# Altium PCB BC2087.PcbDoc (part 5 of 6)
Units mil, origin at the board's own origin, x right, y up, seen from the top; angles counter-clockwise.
Board outline 7401.57 x 1181.1 mil, 6 copper layers (Top Copper, Signal Layer 1, Signal Layer 2, Signal Layer 3, Signal Layer 4, Bottom Copper), stack 62.874 mil thick; 302 components, 237 nets, 1184 pads, 867 vias.
Unrouted connection lines stored in the file: 315.
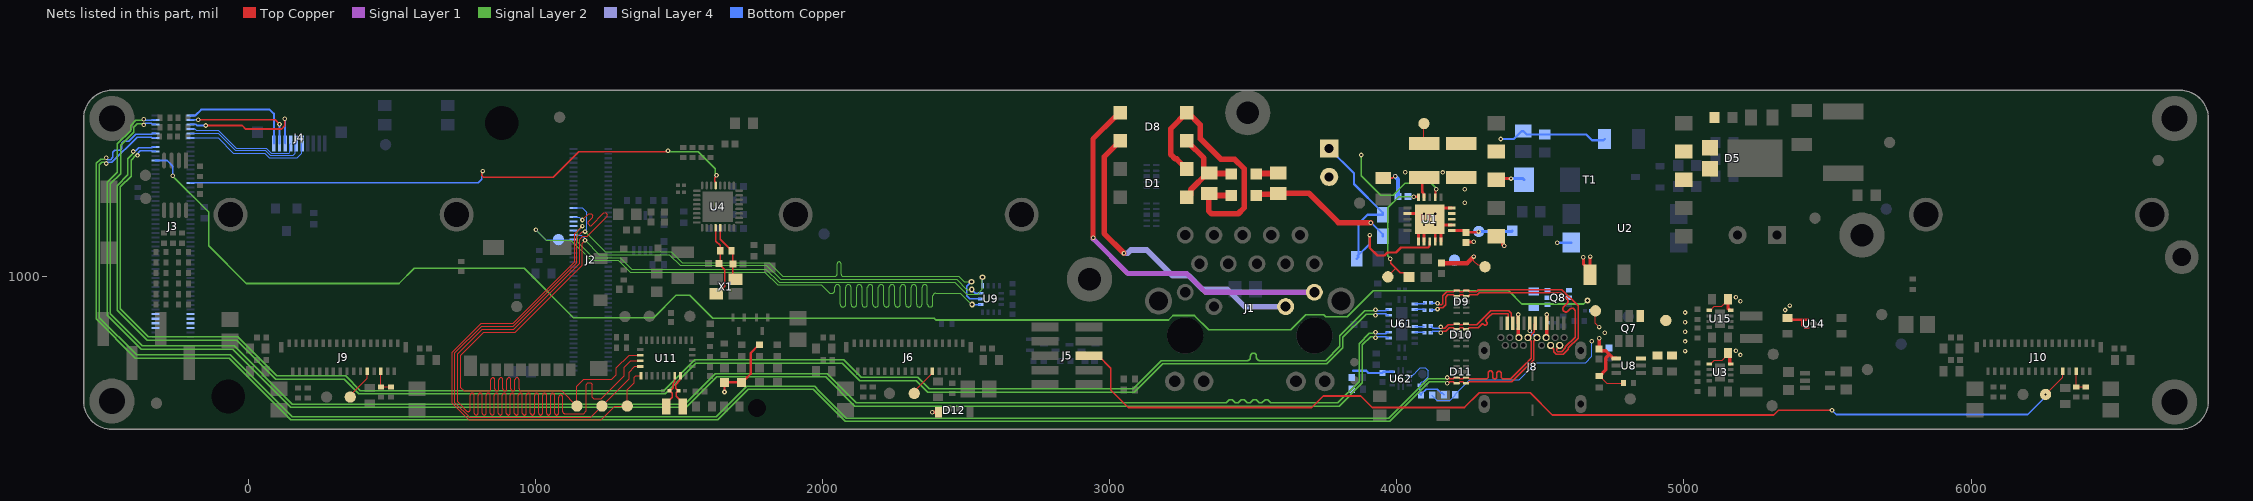
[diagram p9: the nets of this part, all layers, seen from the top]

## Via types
v1: diameter 20, hole 10, Top Copper to Bottom Copper, 273 vias
v2: diameter 16, hole 8, Top Copper to Bottom Copper, tented both sides, 243 vias
v3: diameter 15.98, hole 7.99, Top Copper to Bottom Copper, tented both sides, 201 vias
v4: diameter 18, hole 8, Top Copper to Bottom Copper, tented both sides, 70 vias
v5: diameter 16, hole 7.95, Top Copper to Bottom Copper, tented both sides, 36 vias
v6: diameter 20, hole 10, Top Copper to Bottom Copper, tented both sides, 26 vias
v7: diameter 16, hole 8, Top Copper to Bottom Copper, 17 vias
v8: diameter 19.68, hole 11.81, Top Copper to Bottom Copper, tented both sides, 1 vias

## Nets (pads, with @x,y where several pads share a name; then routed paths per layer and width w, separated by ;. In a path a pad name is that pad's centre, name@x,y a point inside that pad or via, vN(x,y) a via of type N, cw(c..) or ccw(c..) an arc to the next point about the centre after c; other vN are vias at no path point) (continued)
SDS_TXD_P: J3.69 U4.13 | length 2009.5
  Top Copper w5.12: v2(816,1368.72) 812.42,1365.14 812.42,1353.47 818.14,1347.75 1061.94,1347.75 1149.45,1435.26 1457.26,1435.26 v3(1461,1439) ; U4.13@1627.27,1318.86 1627.27,1329.45 1624.5,1332.21 1624.5,1345.97 1629.92,1351.39 v3(1629.92,1354.33)
  Signal Layer 2 w5.12: v3(1461,1439) 1463.32,1436.68 1566.64,1436.68 1625.93,1377.39 1625.93,1358.32 v3(1629.92,1354.33)
  Bottom Copper w5.12: J3.69@-202.76,1326.77 -201.77,1327.76 -189.57,1327.76 -189.07,1328.25 288.17,1328.25 799.25,1328.25 812,1341 812,1364.72 v2(816,1368.72)
SLASEL1: J10.6 R35.2 R36.2 | length 88.2
  Top Copper w4: J10.6@6366.29,671.88 R36.2@6366.29,617.13 R35.2@6399.75,617.13
SLASEL2: J9.6 R40.2 R42.2 | length 89.5
  Top Copper w4: J9.6@460.77,671.88 460.77,617.55 R42.2@461.19,617.13 R40.2@495.79,617.13
SP1: D8.2 J1.13 | length 1092.3
  Top Copper w19.68: D8.2@3035.79,1473.77 2980.31,1418.29 2980.31,1151.57 v3(3049.21,1082.68)
  Signal Layer 4 w19.68: v3(3049.21,1082.68) 3062.01,1082.68 3073.07,1093.74 3128.58,1093.74 3218.38,1003.94 3275.59,1003.94 3322.83,956.69 3409.45,956.69 3469.62,896.52 J1.13@3612.6,896.52
SP2: D8.3 J1.14 | length 1328.6
  Top Copper w17.72: v3(2941.93,1136.81) 2940.94,1137.8 2940.94,1480.32 3018.06,1557.43 3021.03,1557.43 D8.3@3035.79,1572.19
  Signal Layer 1 w17.72: v3(2941.93,1136.81) 2941.93,1132.87 3063.52,1011.28 3268.25,1011.28 3333.01,946.52 J1.14@3712.6,946.52
SPI_BMI270_CS_1V8: J2.60 TP30.1 U9.12 | length 3044.7
  Signal Layer 2 w4: v2(1001,1164) 1036.49,1128.51 1122.79,1128.51 1193.3,1058 1288.3,1058 1329.3,1017 1797.81,1017 1842.81,972 1995.57,972 2024.45,943.12 2030.43,943.12 2032.43,943.12 ccw(c2032.43,952.62) 2041.93,952.62 2041.93,963.15 cw(c2051.43,963.15) 2060.93,963.15 2060.93,904.44 ccw(c2070.43,904.44) 2079.93,904.44 2079.93,963.15 cw(c2089.43,963.15) 2098.93,963.15 2098.93,904.44 ccw(c2108.43,904.44) 2117.93,904.44 2117.93,963.15 cw(c2127.43,963.15) 2136.93,963.15 2136.93,904.44 ccw(c2146.43,904.44) 2155.93,904.44 2155.93,963.15 cw(c2165.43,963.15) 2174.93,963.15 2174.93,904.44 ccw(c2184.43,904.44) 2193.93,904.44 2193.93,963.15 cw(c2203.43,963.15) 2212.93,963.15 2212.93,904.44 ccw(c2222.43,904.44) 2231.93,904.44 2231.93,963.15 cw(c2241.43,963.15) 2250.93,963.15 2250.93,904.44 ccw(c2260.43,904.44) 2269.93,904.44 2269.93,963.15 cw(c2279.43,963.15) 2288.93,963.15 2288.93,904.44 ccw(c2298.43,904.44) 2307.93,904.44 2307.93,963.15 cw(c2317.43,963.15) 2326.93,963.15 2326.93,904.44 ccw(c2336.43,904.44) 2345.93,904.44 2345.93,963.15 cw(c2355.43,963.15) 2364.93,963.15 2364.93,904.75 ccw(c2374.43,904.75) 2383.93,904.75 2383.93,933.62 cw(c2393.43,933.62) 2393.43,943.12 2411.45,943.12 2479.88,943.12 2519.46,903.54 v6(2520.46,903.54)
  Bottom Copper w4: v2(1001,1164) 1035.08,1129.92 TP30.1@1079.49,1129.92 J2.60@1131.69,1129.92
  Bottom Copper w5: v6(2520.46,903.54) U9.12@2549.86,903.54
SPI_BNO08x_CS_1V8: J2.70 U11.18 | length 3669.8
  Top Copper w4: v2(1162.95,1198.42) 1184.46,1219.93 1192.81,1219.93 1198.57,1214.17 1198.57,1207.57 1183,1192 1183,1185.1 1189.1,1179 1194.29,1179 1238.09,1222.8 1245.03,1222.8 1249,1218.83 1249,1212.19 1179.32,1142.51 1164.81,1142.51 1152.76,1130.46 1152.76,1046.76 924.16,818.16 814.16,818.16 728.34,732.34 728.34,564.43 728.42,564.36 760.05,532.72 ccw(c765,537.67) 772,537.67 772,588 cw(c779,588) 786,588 786,525.93 ccw(c793,525.93) 800,525.93 800,588 cw(c807,588) 814,588 814,525.93 ccw(c821,525.93) 828,525.93 828,588 cw(c835,588) 842,588 842,525.93 ccw(c849,525.93) 856,525.93 856,588 cw(c863,588) 870,588 870,525.93 ccw(c877,525.93) 884,525.93 884,588 cw(c891,588) 898,588 898,525.93 ccw(c905,525.93) 912,525.93 912,588 cw(c919,588) 926,588 926,525.93 ccw(c933,525.93) 940,525.93 940,588 cw(c947,588) 954,588 954,525.93 ccw(c961,525.93) 968,525.93 968,588 cw(c975,588) 982,588 982,525.93 ccw(c989,525.93) 996,525.93 996,588 cw(c1003,588) 1010,588 1010,525.93 ccw(c1017,525.93) 1024,525.93 1024,588 cw(c1031,588) 1038,588 1038,525.93 ccw(c1045,525.93) 1052,525.93 1052,588 cw(c1059,588) 1066,588 1066,525.93 ccw(c1073,525.93) 1080,525.93 1080,581.69 cw(c1087,581.69) 1094,581.69 1094,531 ccw(c1101,531) 1101,524 1117,524 1167,524 1176,533 1176,625 1182,631 1192.65,631 1197.86,625.79 1197.86,580.14 1202,576 1217.12,576 1228,576 1307.86,655.86 1307.86,684.83 1330.71,707.68 U11.18@1363.96,707.68
  Bottom Copper w4: J2.70@1131.69,1208.66 1152.71,1208.66 v2(1162.95,1198.42)
SPI_MISO_1V8: J2.64 TP28.1 U9.1 U11.20 | length 3323.9
  Top Copper w4: v5(1162.95,1177.17) 1136,1150.21 1136,1052.63 921.37,838 810.35,838 710,737.65 710,560.15 767.22,502.93 1228.93,502.93 1276,550 TP28.1@1319,550 1319,607 1343,631 1343,651 1348,656 U11.20@1366.42,656
  Signal Layer 2 w4: v5(1162.95,1177.17) 1145.66,1159.87 1145.66,1121.99 1200.65,1067 1294.22,1067 1334.22,1027 1801.42,1027 1847.77,980.65 2460.58,980.65 2501.26,939.97 2539.97,939.97 2556.26,956.26 v6(2556.26,998.74)
  Bottom Copper w4: J2.64@1131.69,1161.42 1148.14,1161.42 1162.95,1176.23 v5(1162.95,1177.17)
  Bottom Copper w5: U9.1@2556.26,969 v6(2556.26,998.74)
SPI_MOSI_1V8: J2.62 TP29.1 U9.14 U11.17 | length 3358.1
  Top Copper w4: v5(1172,1127.43) 1162,1117.43 1162,1040.5 929.5,808 819.35,808 739,727.65 739,614.42 750.42,603 809,603 837,603 ccw(c837,610) 844,610 844,641.53 cw(c851,641.53) 858,641.53 858,610 ccw(c865,610) 872,610 872,641.53 cw(c879,641.53) 886,641.53 886,610 ccw(c893,610) 900,610 900,641.53 cw(c907,641.53) 914,641.53 914,610 ccw(c921,610) 928,610 928,641.53 cw(c935,641.53) 942,641.53 942,610 ccw(c949,610) 949,603 965,603 1091,603 TP29.1@1144,550 1144,620 1166.72,642.72 1264.64,642.72 1280.82,658.9 1280.82,682.82 1325.36,727.36 U11.17@1363.96,727.36
  Signal Layer 2 w4: v5(1172,1127.43) 1221.43,1078 1466.08,1078 1504.08,1040 1804,1040 1853,991 2467,991 2502,956 v6(2519,956)
  Bottom Copper w4: J2.62@1131.69,1145.67 1158.45,1145.67 1172,1132.12 v5(1172,1127.43)
  Bottom Copper w5: v6(2519,956) 2532.09,942.91 U9.14@2549.86,942.91
SPI_SCK_1V8: J2.74 TP27.1 U9.13 U11.19 | length 3343.5
  Top Copper w4: v5(1172,1157.91) 1162.39,1157.91 1144,1139.53 1144,1049.31 922.69,828 811.66,828 719,735.34 719,562.46 770.53,510.93 1191.93,510.93 TP27.1@1231,550 1326,645 1326,668 1345.99,687.99 U11.19@1363.96,687.99
  Signal Layer 2 w4: v5(1172,1157.91) 1241.91,1088 1471.65,1088 1510.86,1048.79 1814.21,1048.79 1860.7,1002.3 2041,1002.3 2043,1002.3 ccw(c2043,1009.3) 2050,1009.3 2050,1045.3 cw(c2057,1045.3) 2064,1045.3 2064,1009.3 ccw(c2071,1009.3) 2071,1002.3 2085,1002.3 2473.11,1002.3 2492.41,983 v6(2518,983)
  Bottom Copper w4: J2.74@1131.69,1240.16 1162.47,1240.16 1178,1224.63 1178,1166.25 1172,1160.25 v5(1172,1157.91)
  Bottom Copper w5: v6(2518,983) 2517.48,983 2502,967.52 2502,934 2512.77,923.23 U9.13@2549.86,923.23
SPI_SIO2: J2.66
SPI_SIO3: J2.68
STRB2: J9.10 TP31.1 | length 114.9
  Top Copper w4: TP31.1@354.18,581.57 354.18,588.23 413.53,647.58 J9.10@413.53,671.88
STRBL: J5.6 J10.10 TP15.1 | length 3690.1
  Top Copper w4: v2(6259.84,590.55) 6319.04,649.75 J10.10@6319.04,671.88
  Top Copper w6: J5.6@2928.15,725.39 2960.43,725.39 3003.5,682.33 3003.5,606.24 3064.74,545 3703.23,545 3743.23,585 3874,585 3914,545 4235.28,545 4286.74,596.46 4464.32,596.46 4541.9,518.88 5312.52,518.88 5329.27,535.62 v2(5515.75,535.62)
  Bottom Copper w6: v2(5515.75,535.62) 5530.62,520.75 6198.06,520.75 6257.93,580.62 6257.93,588.64 v2(6259.84,590.55)
STROBE3: J6.10 TP33.1 | length 103.5
  Top Copper w4: TP33.1@2318.9,594.49 2318.9,601.85 2382.03,664.99 J6.10@2382.03,671.88
SWO: D4.2 T1.3 U1.18 | length 95.2
  Top Copper w10: T1.3@4351.66,1337.72 4356.46,1342.52 v3(4397.64,1342.52)
  Bottom Copper w10: v3(4397.64,1342.52) 4439.26,1342.52 D4.2@4443.19,1338.58
SYS_RST: J3.89 J4.6 | length 457.2
  Bottom Copper w4.02: J3.89@-202.76,1484.25 -106.42,1484.25 -53.5,1431.33 56.79,1431.33 72.82,1415.3 169.06,1415.3 185.08,1431.32 185.08,1463.7 J4.6@186.38,1465
TCK: J3.97 J4.2 | length 383.7
  Top Copper w6: v3(-175.74,1547.24) 92.32,1547.24 v3(107.64,1531.93)
  Bottom Copper w6: J3.97@-202.76,1547.24 v3(-175.74,1547.24) ; J4.2@107.64,1465 v3(107.64,1531.93)
TDI: J3.95 J4.3 | length 452
  Top Copper w6: v3(-149.61,1527.56) -21.88,1527.56 -9.25,1514.93 114.68,1514.93 125.98,1526.24 v3(125.98,1551.18)
  Bottom Copper w6: J3.95@-202.76,1531.5 -184.03,1531.5 -180.09,1527.56 -152.84,1527.56 v3(-149.61,1527.56) ; v3(125.98,1551.18) 126.65,1550.51 126.65,1465.67 J4.3@127.32,1465
TDO: J3.91 J4.5 | length 436.1
  Bottom Copper w4.02: J3.91@-202.76,1500 -105.82,1500 -46.63,1440.8 58.66,1440.8 76.14,1423.32 155.01,1423.32 163.01,1431.32 163.01,1461.32 J4.5@166.69,1465
TMS: J3.99 J4.1 | length 408.1
  Bottom Copper w7.09: J3.99@-202.76,1562.99 -184.8,1562.99 -165.11,1582.68 -68.7,1582.68 73.62,1582.68 87.95,1568.34 J4.1@87.95,1465
TRST: J3.93 J4.4 | length 415.4
  Bottom Copper w4.02: J3.93@-202.76,1515.75 -186.7,1515.75 -181.51,1510.56 -105.05,1510.56 -43.31,1448.82 61.98,1448.82 79.46,1431.33 141.82,1431.33 144.17,1433.69 144.17,1462.16 J4.4@147.01,1465
TXB1_N: C209.2 U61.16 | length 34.4
  Bottom Copper w5.12: U61.16@4062.64,827.06 4071.68,827.06 4071.89,826.85 4094.13,826.85 C209.2@4096.1,828.82
TXB1_P: C208.2 U61.17 | length 34.4
  Bottom Copper w5.12: U61.17@4062.64,807.38 4062.85,807.17 4094.13,807.17 C208.2@4096.1,805.2
TXB_N: C209.1 D10.1 D10.10 J8.A3 | length 363
  Top Copper w5.12: v3(4153.14,825.78) 4157.66,821.26 4166.9,821.26 4178.2,832.57 4196.41,832.57 4199.41,835.56 4199.41,835.91 4200.79,837.29 D10.1@4207.97,837.29 4215.16,837.29 4216.54,835.91 4216.54,835.56 4219.53,832.57 4229.29,832.57 4232.28,835.56 4232.28,835.91 4233.66,837.29 D10.10@4240.85,837.29 4248.03,837.29 4249.41,835.91 4249.41,835.56 4252.41,832.57 4277.74,832.57 4327.79,882.62 4389.82,882.62 4398.82,873.62 4398.82,860.53 4403.54,855.8 J8.A3@4403.54,838.08
  Bottom Copper w5.12: C209.1@4118.15,828.82 4118.94,828.82 4126.76,821 4148.36,821 v3(4153.14,825.78)
TXB_P: C208.1 D10.2 D10.9 J8.A2 | length 360.2
  Top Copper w5.12: v3(4153.14,805.79) 4158.37,811.02 4171.14,811.02 4182.44,822.33 4196.41,822.33 4199.41,819.33 4199.41,818.98 4200.79,817.6 D10.2@4207.97,817.6 4215.16,817.6 4216.54,818.98 4216.54,819.33 4219.53,822.33 4229.29,822.33 4232.28,819.33 4232.28,818.98 4233.66,817.6 D10.9@4240.85,817.6 4248.03,817.6 4249.41,818.98 4249.41,819.33 4252.41,822.33 4281.97,822.33 4282.83,823.19 4293.83,834.19 cw(c4298.42,829.59) 4303.02,834.19 4303.28,833.92 ccw(c4307.88,838.51) 4312.47,833.92 ccw(c4307.88,838.51) 4312.47,843.11 4312.2,843.37 cw(c4316.8,847.97) 4312.2,852.56 4322.3,862.66 4332.03,872.38 4385.58,872.38 4388.58,869.38 4388.58,860.53 4383.86,855.8 J8.A2@4383.86,838.08
  Bottom Copper w5.12: C208.1@4119,805.26 4124.5,810.76 4148.17,810.76 v3(4153.14,805.79)
TXC1_N: C212.2 U61.12 | length 36.2
  Bottom Copper w5.12: U61.12@4062.64,905.8 4063.47,906.63 4094.47,906.63 C212.2@4097.28,909.45
TXC1_P: C211.2 U61.13 | length 35.8
  Bottom Copper w5.12: U61.13@4062.64,886.12 4071.06,886.12 4071.89,886.95 4094.07,886.95 C211.2@4096.89,884.13
TXC_N: C212.1 D9.1 D9.10 J8.B3 | length 838
  Top Copper w5.12: v3(4141.47,908) 4146.23,903.24 4155.43,903.24 4159.28,907.08 4159.28,933.95 4173.36,948.03 4197.46,948.03 4200.46,951.03 4200.46,951.38 4201.84,952.76 D9.1@4209.02,952.76 4216.21,952.76 4217.59,951.38 4217.59,951.03 4220.58,948.03 4230.33,948.03 4233.33,951.03 4233.33,951.38 4234.71,952.76 D9.10@4241.9,952.76 4249.08,952.76 4250.46,951.38 4250.46,951.03 4253.46,948.03 4276.07,948.03 4283.28,955.24 4574.99,955.24 4631.1,899.12 4631.1,786.06 4597.64,752.59 4597.64,748.59 4578.8,729.76 4555.06,729.76 4546.06,738.75 4546.06,748.08 4535.43,758.71 J8.B3@4535.43,761.31
  Bottom Copper w5.12: C212.1@4119.33,909.45 4120.31,908.46 4141,908.46 v3(4141.47,908)
TXC_P: C211.1 D9.2 D9.9 J8.B2 | length 833.2
  Top Copper w5.12: v3(4141.47,888.02) 4146.45,893 4159.67,893 4169.51,902.84 4169.51,929.71 4177.6,937.8 4197.46,937.8 4200.46,934.8 4200.46,934.45 4201.84,933.07 D9.2@4209.02,933.07 4216.21,933.07 4217.59,934.45 4217.59,934.8 4220.58,937.8 4230.33,937.8 4233.33,934.8 4233.33,934.45 4234.71,933.07 D9.9@4241.9,933.07 4249.08,933.07 4250.46,934.45 4250.46,934.8 4253.46,937.8 4280.31,937.8 4287.52,945 4570.75,945 4576.76,938.99 4578.57,937.18 4593.32,922.43 cw(c4585.94,915.05) 4593.32,907.67 4581.12,895.48 ccw(c4588.5,888.1) 4581.12,880.72 ccw(c4588.5,888.1) 4595.88,880.72 4603.06,887.9 cw(c4610.43,880.52) 4620.87,880.52 4620.87,850.61 4620.87,790.3 4587.4,756.83 4587.4,752.83 4574.56,739.99 4559.3,739.99 4556.3,742.99 4556.3,748.08 4566.93,758.71 J8.B2@4566.93,761.31
  Bottom Copper w5.12: C211.1@4118.94,884.13 4120.86,886.06 v3@4139.02,886.06
USB_D_N: D11.2 D11.9 J3.90 J8.A7 J8.B7 | length 6316.1
  Top Copper w5.12: v2(4176,649.76) 4178.94,649.76 4183.83,644.88 4196.41,644.88 4199.41,647.88 4199.41,648.23 4200.79,649.61 D11.9@4207.97,649.61 4215.16,649.61 4216.54,648.23 4216.54,647.88 4219.53,644.88 4229.29,644.88 4232.28,647.88 4232.28,648.23 4233.66,649.61 D11.2@4240.85,649.61 4248.03,649.61 4249.41,648.23 4249.41,647.88 4252.41,644.88 4262.48,644.88 4262.54,644.94 4308.33,644.94 4310.89,644.94 ccw(c4310.89,652.42) 4318.37,652.42 4318.37,665.52 cw(c4325.85,665.52) 4333.33,665.52 4333.33,652.42 ccw(c4340.81,652.42) 4348.29,652.42 4348.29,663.75 cw(c4355.77,663.75) 4363.25,663.75 4363.25,652.42 ccw(c4370.73,652.42) 4370.73,644.94 4396.18,644.94 4417.41,666.17 4467.32,716.08 4467.32,775.64 4456.69,786.27 J8.B7@4456.69,788.87 4459.62,788.87 4478.94,808.19 4478.94,834.74 J8.A7@4482.28,838.08
  Signal Layer 2 w5.17: v5(-496,1395) -500.47,1399.47 -511.03,1399.47 -519.68,1390.82 -519.68,858.27 -389.76,728.35 -63.35,728.35 151.94,513.06 1629.42,513.06 1735.42,619.06 1971.49,619.06 1988.19,602.36 2082.68,507.87 3971.23,507.87 4108.65,645.29 4168.6,645.29 4173.07,649.76 v2(4176,649.76)
  Bottom Copper w5.12: v5(-496,1395) -492.24,1398.76 -476.7,1398.76 -388.46,1487.01 -337.01,1487.01 -334.25,1484.25 J3.90@-324.02,1484.25 ; J8.B7@4456.69,786.27 J8.B7@4456.69,788.87
USB_D_P: D11.1 D11.10 J3.92 J8.A6 J8.B6 | length 6321.6
  Top Copper w5.12: v2(4176,629.76) 4178.94,629.76 4183.83,634.65 4196.41,634.65 4199.41,631.65 4199.41,631.3 4200.79,629.92 D11.10@4207.97,629.92 4215.16,629.92 4216.54,631.3 4216.54,631.65 4219.53,634.65 4229.29,634.65 4232.28,631.65 4232.28,631.3 4233.66,629.92 D11.1@4240.85,629.92 4248.03,629.92 4249.41,631.3 4249.41,631.65 4252.41,634.65 4266.72,634.65 4266.78,634.71 4400.42,634.71 4477.56,711.84 4477.56,775.64 4488.19,786.27 J8.B6@4488.19,788.87 ; J8.A6@4462.6,855.8 J8.A6@4462.6,838.08 4463.03,837.65 v3(4463.03,812.88)
  Signal Layer 2 w5.17: v5(-496,1415) -500.47,1410.53 -515.61,1410.53 -530.75,1395.4 -530.75,853.69 -394.35,717.28 -67.93,717.28 147.36,502 1634,502 1664.14,532.14 1740,608 1966.91,608 2078.1,496.81 3975.81,496.81 4113.23,634.23 4168.6,634.23 4173.07,629.76 v2(4176,629.76)
  Bottom Copper w5.12: v5(-496,1415) -490,1409 -480.94,1409 -474.96,1414.98 -473.15,1416.79 -473.15,1433.76 -466.08,1440.83 -449.11,1440.83 -441.33,1448.61 -441.33,1465.58 -434.26,1472.65 -417.29,1472.65 -405.47,1484.47 -392.7,1497.24 -337.01,1497.24 -334.25,1500 J3.92@-324.02,1500 ; v3(4463.03,812.88) 4463.61,812.88 4487.61,788.87 J8.B6@4488.19,788.87
USB_RX_N: J3.96 U61.4 | length 5660.3
  Signal Layer 2 w5.17: v2(-365,1529.37) -369.47,1533.84 -388.16,1533.84 -400.16,1521.84 -400.16,1503.6 -445.94,1457.83 -445.94,1360 -481,1324.94 -481,871 -369.58,759.58 -50.41,759.58 152.11,557.06 1520.06,557.06 1626.06,663.06 2014.94,663.06 2035,643 2117,561 3400,561 3405.99,561 3416.67,571.68 3426.67,571.68 3437.35,561 3447.35,561 3458.02,571.68 3468.02,571.68 3478.7,561 3488.7,561 3499.38,571.68 3509.38,571.68 3520.06,561 3530.06,561 3540.74,571.68 3550.74,571.68 3561.41,561 3564,561 3794.36,561 3868.94,635.58 3868.94,767.86 3904.14,803.06 3921.03,803.06 v5(3925.65,807.69)
  Bottom Copper w5.12: v2(-365,1529.37) -358.37,1536 -338.76,1536 -334.25,1531.5 J3.96@-324.02,1531.5 ; v5(3925.65,807.69) 3930.69,802.65 3960.47,802.65 3965.2,807.38 U61.4@3972.09,807.38
USB_RX_P: J3.98 U61.3 | length 5658.4
  Signal Layer 2 w5.17: v2(-365,1549.37) -369.47,1544.9 -392.74,1544.9 -411.22,1526.42 -411.22,1508.87 -457,1463.09 -457,1364.58 -492.06,1329.52 -492.06,866.42 -374.16,748.52 -54.99,748.52 147.53,546 1524.64,546 1630.64,652 2010.36,652 2112.42,549.94 3798.94,549.94 3880,631 3880,763.28 3908.72,792 3921.34,792 v5(3925.65,787.69)
  Bottom Copper w5.12: v2(-365,1549.37) -361.87,1546.24 -335.26,1546.24 -334.25,1547.24 J3.98@-324.02,1547.24 ; v5(3925.65,787.69) 3930.38,792.42 3960.47,792.42 3965.2,787.69 U61.3@3972.09,787.69
USB_TX_N: J3.84 U61.8 | length 5434.6
  Signal Layer 2 w5.17: v3(-386.99,1423.22) -392.84,1423.22 -409.45,1406.61 -409.45,1351.12 -446.94,1313.63 -446.94,888.94 -348.82,790.82 -37.47,790.82 98.36,654.98 337.66,654.98 388.58,604.06 1446.88,604.06 1553.82,711 2072.46,711 2133.46,650 2330.64,650 2370.64,610 3081,610 3179.66,708.66 3456.18,708.66 3479.61,708.66 ccw(c3479.61,719.12) 3490.07,719.12 3490.07,724.11 cw(c3500.53,724.11) 3500.53,734.57 cw(c3500.53,724.11) 3510.99,724.11 3510.99,719.12 ccw(c3521.45,719.12) 3521.45,708.66 3544.96,708.66 3752.02,708.66 3801,757.64 3801,794.3 3888.51,881.8 3921.47,881.8 v3(3925.65,885.98)
  Bottom Copper w5.12: v3(-386.99,1423.22) -384.91,1425.3 -384.91,1432.84 -377.99,1439.76 -337.01,1439.76 -334.25,1437.01 J3.84@-324.02,1437.01 ; v3(3925.65,885.98) 3930.25,881.39 3960.47,881.39 3965.2,886.12 U61.8@3972.09,886.12
USB_TX_P: J3.86 U61.7 | length 5437.1
  Signal Layer 2 w5.17: v3(-401.57,1437.01) -401.57,1430.13 -420.51,1411.19 -420.51,1355.7 -458,1318.22 -458,884.36 -353.4,779.75 -42.05,779.75 93.78,643.92 333.08,643.92 384,593 1451.46,593 1558.4,699.94 2067.88,699.94 2128.88,638.94 2326.06,638.94 2366.06,598.94 3085.58,598.94 3184.24,697.6 3756.6,697.6 3812.06,753.06 3812.06,789.71 3893.09,870.74 3920.91,870.74 v3(3925.65,866)
  Bottom Copper w5.12: v3(-401.57,1437.01) -399.5,1439.09 -393.14,1439.09 -382.23,1450 -337.01,1450 -334.25,1452.76 J3.86@-324.02,1452.76 ; v3(3925.65,866) 3930.81,871.16 3960.47,871.16 3965.2,866.43 U61.7@3972.09,866.43
VBUS: C30.2 C73.2 C207.2 J3.80 Q8.1 Q8.2 Q8.5 Q8.6 R69.2 R74.2 R183.2 R187.1 R190.1 TP20.1 U8.1 | length 6570.9
  Top Copper w4.02: TP20.1@4691.93,881.89 4691.93,838.15 v2(4704.72,825.35) ; R183.2@4704.72,654.37 4706.69,654.37 4730.67,630.39 R69.2@4789.37,630.39
  Top Copper w5.91: C207.2@4704.72,749.5 4711.02,743.2 C207.2@4712.88,741.35
  Top Copper w11.81: R183.2@4706.69,654.37 4728.32,675.99 4728.32,717.58 4740.6,729.87 ; C207.2@4711.02,743.2 4727.27,743.2 4740.6,729.87 ; U8.1@4763.78,716.54 4753.94,716.54 4740.6,729.87
  Top Copper w12: C207.2@4704.72,749.5 v2(4704.72,786.06)
  Signal Layer 2 w5.91: v3(-263.78,1352.36) -263.78,1350.78 -139,1226 -139,1108 -8,977 524,977 577,1030 960,1030 1132,858 1411,858 1489,936 1536.39,936 1616.39,856 2388,856 2394,850 3204.33,850 3220.01,865.68 3294.76,865.68 3344.49,815.94 3629.92,815.94 3682.54,868.57 3745.61,868.57 3752.56,861.61 3827.55,861.61 3917.71,951.77 4389.29,951.77 4435.53,905.53 4651.53,905.53 v6(4664,918)
  Bottom Copper w4.02: R187.1@4123.19,588.58 4123.19,586.61 4139.8,570 4186.14,570 4203.74,587.6 R190.1@4203.74,589.57 4203.74,591.54 4212.56,600.35 4253.24,641.03 4426.47,641.03 4487.2,701.77 4657.48,701.77 4679.13,723.43 v2(4679.13,776.08)
  Bottom Copper w5.91: J3.80@-324.02,1405.51 -283.46,1405.51 -263.78,1385.83 v3(-263.78,1352.36)
  other v2: 4724.41,805.63
VBUS_DET: C13.2 R187.2 R190.2 U62.4 | length 281.2
  Bottom Copper w4.02: U62.4@4045.27,653.83 4051.18,653.83 4059.87,662.52 4061.58,662.52 4068.34,669.28 4068.34,669.84 4081.66,683.16 4099.55,683.16 4109.89,672.83 4109.89,652.64 4091.55,634.31 4086.29,634.31 4083.94,631.95 4083.94,626.79 4079.65,622.49 C13.2@4079.53,622.49
  Bottom Copper w6: C13.2@4079.53,622.49 4079.53,592.87 R187.2@4083.82,588.58 4083.82,590.55 4102.07,608.8 4140.52,608.8 4153.72,595.6 4158.34,595.6 R190.2@4164.37,589.57
VBUSIN: C29.2 J8.A4 J8.A9 J8.B4 J8.B9 Q8.4 R74.1 | length 144.7
  Top Copper w12: J8.A4@4423.13,820.46 4422.89,820.21 4422.89,791.18 J8.B9@4425.2,788.87 ; J8.A4@4423.23,838.08 4423.28,838.13 4423.28,869.01 v3(4423.32,869.05) ; J8.B4@4519.68,788.87 4521.56,790.75 4521.56,837.99 J8.A9@4521.65,838.08 v3(4521.65,869.05)
VDD: C22.2 R12.2 TP11.1 U1.5 | length 465.3
  Top Copper w4: TP11.1@3968.5,1000.27 3968.5,1002.46 3996.19,1030.15
  Top Copper w5.91: v3(3976.51,1062.99) 3978.43,1061.06 3978.43,1047.9 3980.31,1046.02 3990.88,1035.46 3992.5,1033.84 3996.19,1030.15 4011.58,1014.76 4027.32,1014.76 R12.2@4042.09,1000
  Top Copper w8: v3(4059.18,1279.53) 4074.01,1279.53 4074.93,1278.61 U1.5@4074.93,1277.56
  Signal Layer 2 w5.91: v3(3976.51,1062.99) 3976.51,1065.72 3968.63,1073.59 3968.63,1240.85 4007.31,1279.53 v3(4059.18,1279.53)
  Bottom Copper w5.91: C22.2@4039.5,1279.53 v3(4059.18,1279.53)
VDD_5V: C14.2 C61.1 C62.1 C65.2 C67.2 C76.2 D3.2 D7.2 D12.1 J3.5 J3.6 J3.7 J3.8 J3.9 J3.10 J3.11 J3.12 Q7.4 R55.2 R213.2 R214.2 TP4.1 U3.1 U3.8 U8.6 U14.3 U14.4 U15.1 U15.8 U62.12 | length 784.8
  Top Copper w4: U3.1@5088.58,697.15 5092.91,697.15 5105.51,709.75 5132.68,709.75 5153.54,730.62 C14.2@5153.54,734.55 ; U15.1@5088.58,883.86 5092.91,883.86 5106,896.95 5132.18,896.95 C67.2@5153.54,918.31
  Top Copper w7.87: v3(1658,599) 1658,632.35 D3.2@1657.48,632.87 D7.2@1717.63,632.87 1729.44,644.69 1730.81,644.69 1749.02,662.89 1749.02,735.24 1777.56,763.78 R55.2@1779.53,763.78
  Top Copper w9.84: C65.2@5360.38,857.28 5366.28,851.38 5378.69,851.38 5379.44,850.62 5411.42,850.62 ; 5432.6,850.62 5411.42,850.62 ; 5433.22,823.22 5421.86,823.22 5413.39,831.69 5413.39,848.66 5411.42,850.62
  Top Copper w11.81: v2(2381.68,528.68) D12.1@2402.88,528.68 ; C14.2@5153.54,734.55 5159.45,728.65 5159.45,697.55 5159.84,697.15 U3.8@5163.39,697.15 ; C67.2@5153.54,922.24 5153.54,918.31 5153.54,890.16 5159.84,883.86 U15.8@5163.39,883.86
  Bottom Copper w7.87: 3848.43,673.51 3893.17,673.51 3901.04,665.64 C76.2@3949.51,665.64 3953.44,669.58 U62.12@3986.22,669.58
  other v2: 5196.85,728.35 5003.94,741.71 5181.1,743.26 5003.94,775.31 5003.94,808.91 5003.94,842.52 5003.94,876.12 5352.36,884.84 5368.11,900.23 5196.85,915.49 5181.1,929.13
VNEG: C8.1 FB3.2 R10.1 TP13.1 U1.7 U1.11 U1.12 U1.14 U1.15 U1.17 U1.20 U1.21 | length 1045.9
  Top Copper w9.84: U1.7@4037.53,1220.47 v7(4094.62,1220.47) U1.21@4114.3,1200.79 ; U1.11@4074.93,1124.02 4074.93,1161.42 v7(4094.62,1181.1) ; U1.12@4094.62,1124.02 v7(4094.62,1181.1) ; U1.14@4133.99,1124.02 v7(4133.99,1181.1) ; U1.15@4153.67,1124.02 4153.67,1161.42 v7(4133.99,1181.1) ; U1.17@4191.07,1181.1 v7(4133.99,1181.1) ; U1.20@4191.07,1240.16 4153.67,1240.16 v7(4133.99,1220.47) U1.21@4114.3,1200.79 ; v7(4094.62,1181.1) U1.21@4114.3,1200.79 ; U1.21@4114.3,1200.79 v7(4133.99,1181.1)
  Top Copper w19.68: FB3.2@3509.73,1283.46 3513.67,1287.4 3582.68,1287.4 C8.1@3586.61,1291.34 3693.9,1291.34 3796.26,1188.98 v3(3909.45,1188.98)
  Bottom Copper w7.87: v3(3909.45,1188.98) 3910.56,1188.98 3950.92,1148.62 R10.1@3950.92,1141.73
VNEG_IN: C33.1 D1.4 D8.4 FB3.1 | length 968.6
  Top Copper w19.68: D1.4@3268.08,1375.98 3232.97,1411.09 3228.09,1411.09 3212.6,1426.58 3212.6,1516.72 D8.4@3268.08,1572.19 3272.37,1572.19 3315,1529.56 3315,1481.79 3386.79,1410 3435,1410 3467.8,1377.2 3467.8,1240.41 3447.39,1220 3354.23,1220 3344.23,1230 3344.23,1289.11 C33.1@3346.46,1291.34 3354.33,1283.46 FB3.1@3423.12,1283.46
VPOS: C1.2 C2.1 C3.2 C4.2 C8.2 C26.1 FB2.2 R4.2 R8.1 R11.1 T1.4 TP5.1 U1.2 U1.13 | length 1886.9
  Top Copper w4: TP5.1@4094.49,1534.15 4094.49,1464.7 C1.2@4094.62,1464.57
  Top Copper w7.87: v3(3905.51,1145.67) 3905.51,1100.92 3932.18,1074.25 3956.75,1074.25 3967.42,1084.92 3996.89,1084.92 4014.33,1102.36 4066.66,1102.36 4066.72,1102.3 4108.64,1102.3 4113.32,1106.97 4113.32,1123.03 U1.13@4114.3,1124.02 ; U1.2@4133.99,1277.56 4133.99,1286.42 4134.97,1287.4 4134.97,1300.81 4137.52,1303.36 v3(4137.52,1305.55)
  Top Copper w19.68: FB2.2@3509.73,1358.27 3511.7,1360.24 3584.65,1360.24 C8.2@3586.61,1362.2
  Signal Layer 2 w5.91: v3(3875.83,1424.58) 3875.83,1352.55 3943.51,1284.87 ; 3962.18,1284.87 3943.51,1284.87 ; v3(4137.52,1305.55) 4137.52,1308.28 4132.23,1313.57 4132.23,1313.72 4119.96,1325.99 4028.17,1325.99 3987.06,1284.87 3943.51,1284.87
  Bottom Copper w7.87: C2.1@3764.34,1446.85 3850.39,1360.79 3850.39,1323.95 3950.92,1223.43 R11.1@3950.92,1216.54 3897.64,1216.54 3866.14,1185.04 3866.14,1073.57 3866.14,1068.77 R8.1@3860.36,1062.99 ; R8.1@3864.05,1073.57 3905.51,1115.03 v3(3905.51,1145.67) ; v3(4362.2,1480.32) 4407.05,1480.32 4434.61,1507.87 C4.2@4440.52,1507.87 4452.33,1496.06 4659.77,1496.06 4679.46,1476.38 4720.04,1476.38 C26.1@4723.98,1480.31
VPOS_IN: C33.2 D1.1 D8.1 FB2.1 | length 362.4
  Top Copper w19.68: D1.1@3268.08,1277.56 3270.52,1275.12 3281.86,1286.46 3281.86,1303.51 3340.55,1362.2 3327.76,1375 3327.76,1414.09 3272.97,1468.88 D8.1@3268.08,1473.77 3277.86,1473.77 D8.1@3279.33,1475.24 ; C33.2@3337.21,1371.45 C33.2@3346.46,1362.2 ; C33.2@3348.43,1362.2 3350.39,1360.24 3421.15,1360.24 FB2.1@3423.12,1358.27
VSEC: C5.2 D5.2 T1.7 T1.8
VSS: C1.1 C2.2 C3.1 C11.1 C22.1 C24.1 C25.1 R13.2 T1.1 TP12.1 U1.4 U1.19 U2.3 | length 638.1
  Top Copper w4: v3(4267.71,1070.86) 4267.71,1055.26 4281.4,1041.56 4300.96,1041.56 TP12.1@4307.09,1035.43
  Top Copper w5.91: R13.2@3952.76,1344.49 3985.97,1344.49 3991.88,1350.39 v3(3994.09,1350.39)
  Top Copper w9.84: U1.4@4094.62,1277.56 4094.62,1289.3 4088.36,1295.55 4088.36,1340.2 C1.1@4094.62,1346.46 ; C11.1@4239.3,1121.06 C11.1@4240.29,1120.08 4241.27,1121.06 4266.86,1121.06 v3(4267.85,1122.05) ; v3(4649.61,1068.2) 4649.61,1044.29 4658.46,1035.43 C25.1@4673.23,1035.43 ; C25.1@4673.23,1007.87 C25.1@4673.23,1035.43 ; v2(4673.22,1070.86) 4673.22,1057.42 C25.1@4673.23,1035.43
  Top Copper w15: C24.1@4156.26,1047.91 4244.75,1047.91 v3(4267.71,1070.86) ; T1.1@4347.01,1141.73 4347.57,1142.29 4347.57,1153.54 4370.02,1131.09 4370.02,1112.66 4374.14,1108.54 v3(4374.14,1108.27)
  Bottom Copper w9.84: v3(4558.63,1119.29) U2.3@4607.45,1119.29
  Bottom Copper w15: v3(3994.09,1350.39) 3994.09,1350.13 4004.07,1340.16 C22.1@4004.07,1279.53
  other v3: 4236.22,1257.87 4236.34,1305.05 4159.53,1363.91 4029.45,1365.06
VT15V: C11.2 D2.1 TP8.1 U1.16 | length 215.5
  Top Copper w10: U1.16@4191.07,1161.42 4191.15,1161.34 4234.46,1161.34 C11.2@4240.29,1155.51 4279.63,1155.51 4281.99,1157.87 v3(4284.7,1157.87)
  Bottom Copper w10: v3(4284.7,1157.87) TP8.1@4285.29,1158.46 4400.16,1158.46 D2.1@4402.13,1160.43
XI: C48.2 R47.1 U4.28 X1.1 | length 262.2
  Top Copper w5: U4.28@1627.27,1171.22 1627.27,1125 1642.72,1109.55 R47.1@1642.72,1090.98 1642.72,1050.5 C48.2@1638.19,1045.98 1659.35,1024.81 1659.35,967.04 1633.17,940.86 X1.1@1629.23,940.86
XIN: C28.2 U11.27 Y1.1 | length 131.3
  Top Copper w5: C28.2@1497.7,603.1 C28.2@1496.91,603.1 ; U11.27@1504.21,656 1502.2,653.99 1502.2,639.2 1488,625 1488,612.02 C28.2@1496.91,603.1 ; Y1.1@1512.03,548.35 1512.03,561.15 1489.45,583.73 1489.45,595.64 C28.2@1496.91,603.1
XO: C49.2 R47.2 U4.29 X1.3 | length 201.2
  Top Copper w5: U4.29@1643.01,1171.22 1643.01,1132.02 1687.21,1087.83 C49.2@1687.21,1045.76 1687.21,1000.99 X1.3@1696.16,992.04
XOUT: C27.2 U11.26 Y1.2 | length 130.2
  Top Copper w5: Y1.2@1454.55,548.35 1454.55,561.15 1475,581.6 1475,594.46 1466.36,603.1 C27.2@1465.57,603.1 1469.37,606.9 1472.5,606.9 1479,613.4 1479,629 1484.53,634.53 U11.26@1484.53,656
pads on no net: FID1.1 FID2.1 FID3.1 FID4.1 FID5.1 FID6.1 J1. J2.4 J2.6 J2.10 J2.12 J2.16 J2.18 J2.22 J2.24 J2.42 J2.45 J2.46 J2.48 J2.49 J2.51 J2.52 J2.54 J2.55 J2.57 J2.69 J3.17 J3.19 J3.21 J3.23 J3.25 J3.27 J3.31 J3.33 J3.35 J3.37 J3.41 J3.43 J3.45 J3.47 J3.48 J3.50 J3.51 J3.53 J3.56 J3.58 J3.76 J4.11 J4.12 J5.3 J6.0 J8.A8 J8.B8 J8.G2 J9.0 J9.13 J9.14 J9.16 J9.17 J10.0 J10.13 J10.14 J10.16 J10.17 T1.5 T1.6 U3.6 U8.4 U9.2 U9.3 U9.10 U9.11 U10.4 U11.1 U11.7 U11.8 U11.12 U11.13 U11.21 U11.22 U11.23 U11.24 U15.6 U62.9

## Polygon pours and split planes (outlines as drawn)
GND on Top Copper "GND_L01_P071" (solid, remove dead copper, pour order 71): -574.82,567.2 ccw(c-476.39,567.2) -476.39,468.77 6728.33,468.77 ccw(c6728.33,567.2) 6826.76,567.2 6826.76,1551.45 ccw(c6728.33,1551.45) 6728.33,1649.88 -476.39,1649.88 ccw(c-476.39,1551.45) -574.82,1551.45
2V8_L on Top Copper "2V8_L_L01_P002" (solid, pour order 2): 5957.64,723.07 5955.35,720.78 5955.35,605.85 5976.55,584.65 6043.19,584.65 6053,594.46 6053,646.08 6037.53,661.55 6037.53,710.54 6025,723.07
1V2_L on Top Copper "1V2_L_L01_P003" (solid, pour order 3): 5831.13,902 5822.83,893.7 5822.83,797.17 5825,795 5861.59,795 5884.02,817.43 5940.03,817.43 5951.08,806.38 5951.08,737.13 5954.94,733.27 5998.16,733.27 6007.26,742.37 6007.26,784.55 6016.76,794.04 6094.34,794.04 6094.34,838.48 6075.36,857.47 6037.53,857.47 5993,902
2V8_CAM_M on Top Copper "2V8_CAM_M_L01_P004" (solid, pour order 4): 2026.12,723.98 2022.92,720.78 2022.92,593.54 2035,581.46 2109.43,581.46 2116.29,588.32 2116.29,646.98 2098.28,664.99 2098.28,716.1 2090.4,723.98
1V2_CAM_M on Top Copper "1V2_CAM_M_L01_P005" (solid, pour order 5): 2095.71,927.56 1890.9,927.56 1884.51,921.17 1884.51,828.71 1893.07,820.15 2043.08,820.15 2053.4,809.82 2053.4,778.68 2058.05,774.03 2093.55,774.03 2108.33,788.81 2108.33,914.95
2V8_R on Top Copper "2V8_R_L01_P007" (solid, pour order 7): 54.9,722.5 47.4,715 47.4,597.07 62.77,581.69 140.91,581.69 145.83,586.61 145.83,643.13 129.77,659.18 129.77,714.63 121.9,722.5
1V2_R on Top Copper "1V2_R_L01_P010" (solid, pour order 10): 172.94,910 182.92,900.02 182.92,821.18 162.13,800.39 98.39,800.39 93,795 93,742.63 82.87,732.5 45.69,732.5 45.69,816.22 39.68,822.23 -94,822.23 -102.77,831 -102.77,887.26 -80.03,910
VDD_5V on Top Copper "VDD_5V_L01_P048_DC" (solid, remove dead copper, pour order 73): 5342.66,843.5 5342.66,906.13 5349.55,913.02 5373.54,913.02 5378.09,908.46 5378.09,843.5
3V3 on Top Copper "3V3_TL_DC" (solid, remove dead copper, pour order 74): 5273.62,582.98 5273.62,614.47 5244.49,643.61 5153.54,643.61 5153.54,633.48 5139.76,619.7 5139.76,582.98 5108.27,551.48 5108.27,535.43 5177.17,535.43 5188.98,547.24 5188.98,582.98
VSS on Top Copper "VSS_L01_P075" (solid, remove dead copper, pour order 75): 3742.54,1581.38 4758.89,1581.38 4765.97,1574.3 4765.97,1003.02 4727.51,964.57 3941.87,964.57 3819.31,1087.13 3819.31,1215.38 3685.59,1349.1 3687.23,1350.73 3687.23,1525.09
1V2 on Top Copper "1V2_L01_P062_DC" (solid, remove dead copper, pour order 25): 1893.7,806.52 1893.7,523.62 1964.57,523.62 1964.57,806.52
1V2 on Top Copper "1V2_L01_P061_DC" (solid, remove dead copper, pour order 24): -77.76,815.89 -77.76,759.84 9.02,759.84 9.02,815.89
VDD_5V on Top Copper "VDD_5V_L01_P044_DC" (solid, remove dead copper, pour order 20): 5011.81,897.64 5023.62,885.83 5023.62,705.71 4825.79,705.71 4825.79,897.64
5V_PoE on Top Copper "5V_POE_L01_P041_DC" (solid, remove dead copper, pour order 19): 5625.2,1386.5 5621.94,1389.76 5468.5,1389.76 5255.91,1177.17 5255.91,1124.29 5198.54,1066.93 4900.74,1066.93 4755.91,922.09 4744.4,910.59 4744.4,756.69 4826.77,756.69 4826.77,893.39 4831.02,897.64 4967.67,897.64 5018.85,948.82 5275.59,948.82 5543.31,1216.54 5598.43,1216.54 5625.2,1243.31 5625.2,1388.58
2V8 on Top Copper "2V8_L01_P023_DC" (solid, remove dead copper, pour order 61): 5481.14,863.19 5515.59,897.64 5620.08,897.64 5627.95,889.76 5627.95,847.44 5624.02,843.5 5481.14,843.5
VBUS on Top Copper "VBUS_L01_P043_DC" (solid, remove dead copper, pour order 21): 4777.87,837.24 4725.75,837.24 4692.91,837.24 4692.91,767.36 4693.9,768.34 4777.87,768.34
PCIE_1V0 on Top Copper "PCIE_1V0_L01_P020_DC" (solid, remove dead copper, pour order 54): 1402.34,1029.09 1441.71,1029.09 1551.69,1029.09 1551.69,975.65 1530.04,954 1530.04,932.34 1494.61,932.34 1433.3,993.65 1402.34,993.65
PCIE_1V0 on Top Copper "PCIE_1V0_L01_P058_DC" (solid, remove dead copper, pour order 22): 1414.19,1078.15 1358.66,1078.15 1346.46,1065.94 1346.46,993.98 1441.38,993.98 1441.71,993.65 1441.71,1078.18
VDD_5V on Top Copper "VDD_5V_L01_P047_DC" (solid, remove dead copper, pour order 26): 5139.76,752.27 5202.39,752.27 5209.28,745.38 5209.28,721.39 5204.72,716.84 5139.76,716.84
VDD_5V on Top Copper "VDD_5V_L01_P046_DC" (solid, remove dead copper, pour order 72): 5139.76,939.96 5202.39,939.96 5209.28,933.07 5209.28,909.08 5204.72,904.53 5139.76,904.53
VPOS on Top Copper "VPOS_L01_P002_DC" (solid, remove dead copper, pour order 34): 3615.16,1339.57 3685.04,1409.45 4382.02,1409.45 4382.02,1500 3641.73,1500 3558.07,1416.34 3558.07,1339.57
ISNS on Top Copper "ISNS_L01_P005_DC" (solid, remove dead copper, pour order 44): 4051.31,1205.71 4009.14,1205.71 3980.31,1234.9 3980.31,1290.35 3925.2,1290.35 3925.2,1203.87 3933.2,1195.87 4051.31,1195.87
SWO on Top Copper "SWO_L01_P004_DC" (solid, remove dead copper, pour order 43): 4177.22,1205.71 4219.55,1205.71 4255.96,1242.13 4255.96,1363.58 4381.95,1363.58 4381.95,1313.58 4338.05,1269.69 4318.96,1269.69 4318.96,1255.91 4258.92,1195.87 4177.22,1195.87
VSS on Top Copper "VSS_L01_P003_DC" (solid, remove dead copper, pour order 41): 4177.29,1215.55 4223.55,1215.55 4256.03,1248.03 4256.03,1300.89 4277.69,1322.54 4277.69,1374.02 3760.95,1374.17 3732.84,1374.02 3745.46,1374.09 3732.84,1361.47 3732.84,1335.46 3749.4,1318.9 4211.66,1318.9 4211.66,1232.2 4204.85,1225.39 4177.29,1225.39
VSEC on Top Copper "VSEC_L01_P007_DC" (solid, remove dead copper, pour order 46): 5124.02,1574.8 5124.02,1482.17 5118.82,1476.97 5118.82,1349.8 5063.7,1349.8 5029.53,1315.63 5029.53,1313.58 4968.5,1313.58 4968.5,1462.01 5029.53,1462.01 5043.31,1475.79 5043.31,1570.87 5047.24,1574.8 5088.58,1574.8
NetC6_2 on Top Copper "NetC6_2_TL_DC" (solid, remove dead copper, pour order 47): 5477.56,1481.1 5530.32,1481.1 5530.32,1621.26 5475.2,1621.26 5475.2,1549.02 5444.88,1518.7 5374.02,1518.7 5334.84,1479.53 5152.36,1479.53 5152.36,1347.24 5343.7,1347.24
NetL4_1 on Top Copper "NETL4_1_L01_P025_DC" (solid, remove dead copper, pour order 70): 5153.54,682.98 5173.74,682.98 5183.98,693.21 5273.62,693.21 5273.62,661.72 5183.46,661.72 5173.23,671.95 5153.54,671.95
NetL3_1 on Top Copper "NETL3_1_L01_P025_DC" (solid, remove dead copper, pour order 67): 5153.54,869.69 5173.74,869.69 5183.98,879.92 5273.62,879.92 5273.62,848.43 5183.46,848.43 5173.23,858.66 5153.54,858.66
1V8 on Top Copper "1V8_L01_P023_DC" (solid, remove dead copper, pour order 62): 5629.87,710.68 5658.32,710.68 5662.32,706.68 5662.32,661.34 5653.7,652.72 5490.8,652.72 5490.8,676.36 5525.25,710.81 5629.74,710.81
1V2 on Top Copper "1V2_L01_P021_DC" (solid, remove dead copper, pour order 58): 5153.54,830.32 5244.49,830.32 5273.62,801.18 5273.62,769.69 5194.88,769.69 5193.59,770.98 5139.76,770.98 5139.76,806.41 5153.54,820.19
REGOUT on Top Copper "REGOUT_TL_DC" (solid, remove dead copper, pour order 48): 1472.95,1066.2 1551.69,1066.2 1551.69,1166.51 1571.76,1186.58 1571.76,1197.8 1532.74,1197.8 1472.95,1138.01 1472.95,1087.77
GND on Signal Layer 4 "GND_L05_P051" (solid, remove dead copper, pour order 51): -574.66,567.36 ccw(c-476.23,567.36) -476.23,468.93 6728.49,468.93 ccw(c6728.49,567.36) 6826.92,567.36 6826.92,1551.61 ccw(c6728.49,1551.61) 6728.49,1650.03 -476.23,1650.03 ccw(c-476.23,1551.61) -574.66,1551.61
VNEG on Signal Layer 4 "VNEG_L05_P063" (solid, remove dead copper, pour order 63): 3751.17,1574.01 4767.53,1574.01 4774.61,1566.93 4774.61,1109.25 4711.61,1046.26 3926.18,1046.26 3867.3,1105.14 3867.3,1276.3 3845.47,1298.13 3737.82,1298.13 3694.23,1341.73 3695.87,1343.36 3695.87,1517.72
1V2 on Signal Layer 4 "1V2_L05_P042" (solid, remove dead copper, pour order 42): 5244.09,830.01 5271.65,802.45 5271.65,720.47 5020.11,468.93 117.68,468.93 -66.93,653.54 -66.93,877.95 -55.12,889.76 78.74,889.76 94.49,874.02 94.49,722.51 155.58,661.42 4988.19,661.42 5157.48,830.71
VBUS on Signal Layer 4 "VBUS_L05_P042_DC" (solid, remove dead copper, pour order 38): 4670,767.72 4677.21,760.51 4736.88,760.51 4744.09,767.72 4744.09,831 4737,838 4677.35,838 4670,830.65
GND on Signal Layer 1 "GND_L02_P037" (solid, remove dead copper, pour order 37): -574.66,567.36 ccw(c-476.23,567.36) -476.23,468.93 6728.49,468.93 ccw(c6728.49,567.36) 6826.92,567.36 6826.92,1551.61 ccw(c6728.49,1551.61) 6728.49,1650.03 -476.23,1650.03 ccw(c-476.23,1551.61) -574.66,1551.61
VNEG on Signal Layer 1 "VNEG_L02_P031" (solid, remove dead copper, pour order 31): 3683.07,1503.94 4208.79,1503.94 4208.79,1092.87 4314.7,986.96 3683.07,986.96
VSS on Signal Layer 1 "VSS_L02_P030" (solid, remove dead copper, pour order 30): 3984.25,1503.94 4775.59,1503.94 4775.59,952.76 4354.33,952.76 4212.6,1094.49 4212.6,1314.96 3984.25,1314.96
GND on Bottom Copper "GND_L06_P069" (solid, remove dead copper, pour order 69): -580.76,567.1 ccw(c-482.34,567.1) -482.34,468.67 6722.39,468.67 ccw(c6722.39,567.1) 6820.81,567.1 6820.81,1551.35 ccw(c6722.39,1551.35) 6722.39,1649.78 -482.34,1649.78 ccw(c-482.34,1551.35) -580.76,1551.35
VBUSIN on Bottom Copper "VBUSIN_L06_P032" (solid, pour order 32): 4530.9,908.32 4530.9,836.65 4399.77,836.65 4393.7,842.72 4393.7,902.51 4399.5,908.32
VBUS on Bottom Copper "VBUS_L06_P033" (solid, pour order 33): 4457.36,988 4450.36,981 4450.36,928.87 4459.23,920 4647.24,920 4668,899.24 4668,760 4688,740 4749,740 4764,755 4764,953 4729,988
VDD_5V on Bottom Copper "VDD_5V_L06_P050_DC" (solid, remove dead copper, pour order 50): -20.38,877.38 77.38,877.38 141.54,813.22 141.09,715.91 211.33,645.67 570.87,645.67 574.8,641.73 1374.02,641.73 1433.07,700.79 1972.44,700.79 2059.06,614.17 2059.06,602.36 2362.2,602.36 2476.38,716.54 3822.83,716.54 3866.14,673.23 4826.77,673.23 4889.76,736.22 4889.76,854.33 4974.76,939.33 5376.57,939.33 5376.57,468.93 71,468.93 71,605 -23,699 -359.76,699 -389.76,729 -389.76,877.95 -20.95,877.95
VNEG on Bottom Copper "VNEG_L06_P068" (solid, remove dead copper, pour order 68): 3694.88,1582.68 4774.61,1582.68 4774.61,1007.87 4126.11,1007.87 3694.88,1007.87
GND on Signal Layer 3 "GND_L04_P060" (solid, remove dead copper, pour order 60): -574.66,567.36 ccw(c-476.23,567.36) -476.23,468.93 6728.49,468.93 ccw(c6728.49,567.36) 6826.92,567.36 6826.92,1551.61 ccw(c6728.49,1551.61) 6728.49,1650.03 -476.23,1650.03 ccw(c-476.23,1551.61) -574.66,1551.61
VNEG on Signal Layer 3 "VNEG_L04_P066" (solid, remove dead copper, pour order 66): 3723.52,1511.37 4773.48,1511.37 4773.48,1102.91 4710.49,1039.91 3975.84,1039.91 3865.21,1150.54 3865.21,1189.91 3723.52,1331.6
3V3 on Signal Layer 3 "3V3_L3_DC" (solid, remove dead copper, pour order 56): 4976.38,535.43 5177.17,535.43 5188.98,547.24 5188.98,665.35 4807.09,1047.24 3968.5,1047.24 3866.14,1149.61 3866.14,1259.84 3755.91,1370.08 1652.99,1365.59 1570.87,1283.46 1263.78,1283.46 972.44,992.13 972.44,700.79 976.38,696.85 980.31,700.79 1007.87,700.79 1007.87,807.32 1365.91,1165.35 1881.18,1165.35 1928.42,1212.6 3681.1,1212.6 3724.41,1169.29 3724.41,1095.33 3882.73,937.01 3968.5,937.01 4074.8,830.71 4681.1,830.71
PCIE_1V0 on Signal Layer 3 "PCIE_1V0_L04_P057_DC" (solid, remove dead copper, pour order 35): 1477.74,1062.99 1446.52,1031.76 1346.46,1031.11 1346.46,1131.57 1368.43,1153.54 1653.02,1153.54 1732.78,1233.3 1763.28,1233.3 1763.28,1168.8 1657.48,1062.99
GND on Signal Layer 2 "GND_L03_P036" (solid, remove dead copper, pour order 36): -574.66,567.36 ccw(c-476.23,567.36) -476.23,468.93 6728.49,468.93 ccw(c6728.49,567.36) 6826.92,567.36 6826.92,1551.61 ccw(c6728.49,1551.61) 6728.49,1650.03 -476.23,1650.03 ccw(c-476.23,1551.61) -574.66,1551.61
VSS on Signal Layer 2 "VSS_L03_P064" (solid, remove dead copper, pour order 64): 3750,1558.07 4766.36,1558.07 4773.43,1550.99 4773.43,1093.32 4710.44,1030.32 3903.64,1030.32 3826.77,1107.19 3826.77,1192.07 3693.06,1325.79 3694.69,1327.43 3694.69,1501.78

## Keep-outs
Top Copper:
  lines w5.91: 2903,1667 2903,1129 2943,1089 2969,1089 3024,1034 3104.27,1034 3269.27,1199 3736.61,1199 3831.69,1103.91 3831.69,1066.61 ; 3349,1670 3349,1483 3394.09,1437.91 3546.66,1437.91 3633.75,1525 3673.79,1525 3696.17,1525 4026.32,1525 4082.03,1580.71 4687.01,1580.71 4763.78,1503.94 4763.78,1099.41 4720.47,1056.1 4720.47,962.6 4620.08,962.6 4587.6,995.08 4187.53,995.08 4159.85,967.4 3930.2,967.4 3831.69,1065.91
Signal Layer 1:
  lines w5.91: 3685.48,1307.89 3685.04,1308.33 ; 4713.42,1503.94 3720.47,1503.94 3685.04,1468.5 3685.04,1308.33 ; 4713.58,1503.94 4775.59,1441.93 4775.59,1114.62 4716.54,1055.56 4716.54,967.37 4711.16,962 4623,962 4590,995 4424.66,995 4188.81,995 3982.01,995 3904.47,995 3884.85,1014.62 3791.34,1108.13 3791.34,1202.03 3685.04,1308.33
Signal Layer 2:
  lines w5.91: 3696.85,1314.96 3799.21,1212.6 3826.77,1185.04 3826.77,1102.36 3901.57,1027.56 3959.48,1027.56 4465.94,1028.56 4714.56,1028.56 4775.59,1089.59 4775.59,1460.32 4733.53,1502.38 4731.97,1503.94 3740.16,1503.94 3696.85,1460.63 3696.85,1314.96
Signal Layer 3:
  lines w5.91: 3696.85,1354.89 3696.85,1360.08 3696.85,1491.14 3719.49,1513.78 4739.47,1513.78 4775.59,1477.66 4775.59,1116.12 4716.54,1057.07 4706.71,1047.24 3968.5,1047.24 3866.14,1149.61 3866.14,1253.6 3821.72,1298.02 3756.73,1298.02 3753.71,1298.02 3696.85,1354.89
Signal Layer 4:
  lines w5.91: 3866.14,1159.32 3866.14,1275.59 3843.6,1298.13 3740.44,1298.13 3696.85,1341.73 3696.85,1519.68 3751.97,1574.8 4768.03,1574.8 4775.59,1567.24 4775.59,1115.75 4716.54,1056.69 4716.54,1047.24 4444.88,1047.24 3947.91,1047.24 3925.2,1047.24 3866.14,1106.3 3866.14,1172.43
Bottom Copper:
  lines w5.91: 3692.91,1298.02 3795.28,1195.66 3795.28,1049.06 3828.21,1016.12 3897.15,1016.12 3944.11,1016.12 4472.44,1016.12 4653.26,1016.12 4712.6,1016.12 4712.6,1057.07 4771.65,1116.12 4771.65,1567.61 4764.09,1575.18 3748.03,1575.18 3692.91,1520.06 3692.91,1298.02

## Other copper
Top Copper:
  pour cut-out: 2905,1675 2905,1159 2976.1,1087.9 3149.22,1087.9 3340,1278.68 3340,1750

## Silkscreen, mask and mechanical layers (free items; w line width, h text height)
Top Overlay:
  lines w6: -345,903.41 -335,903.41 ; -345,937.99 -335,937.99 ; -345,977.36 -335,977.36 ; -345,1013.78 -335,1013.78 ; -195,1050 -180,1050 ; -195,1087.01 -180,1087.01
  text ".project_title  .revision" at 939.18,1326.15 h59.06
  text "BOOT7" at -175,1077.4 h35
  text "BOOT0" at -174,1037 h35
  text "BOOT1" at -455,1004.17 h35
  text "BOOT2" at -455,966.92 h35
  text "BOOT3" at -455,925.39 h35
  text "BOOT4" at -455,890.39 h35
Bottom Overlay:
  drawing of 10 lines, arcs and shapes, not listed
  text ".project_title  .revision" at 6282.84,1140.53 h59.06 r270
Bottom Mask:
  drawing of 3 lines, arcs and shapes, not listed
Board:
  drawing of 6072 lines, arcs and shapes, not listed
out line:
  the board outline again, w3.94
